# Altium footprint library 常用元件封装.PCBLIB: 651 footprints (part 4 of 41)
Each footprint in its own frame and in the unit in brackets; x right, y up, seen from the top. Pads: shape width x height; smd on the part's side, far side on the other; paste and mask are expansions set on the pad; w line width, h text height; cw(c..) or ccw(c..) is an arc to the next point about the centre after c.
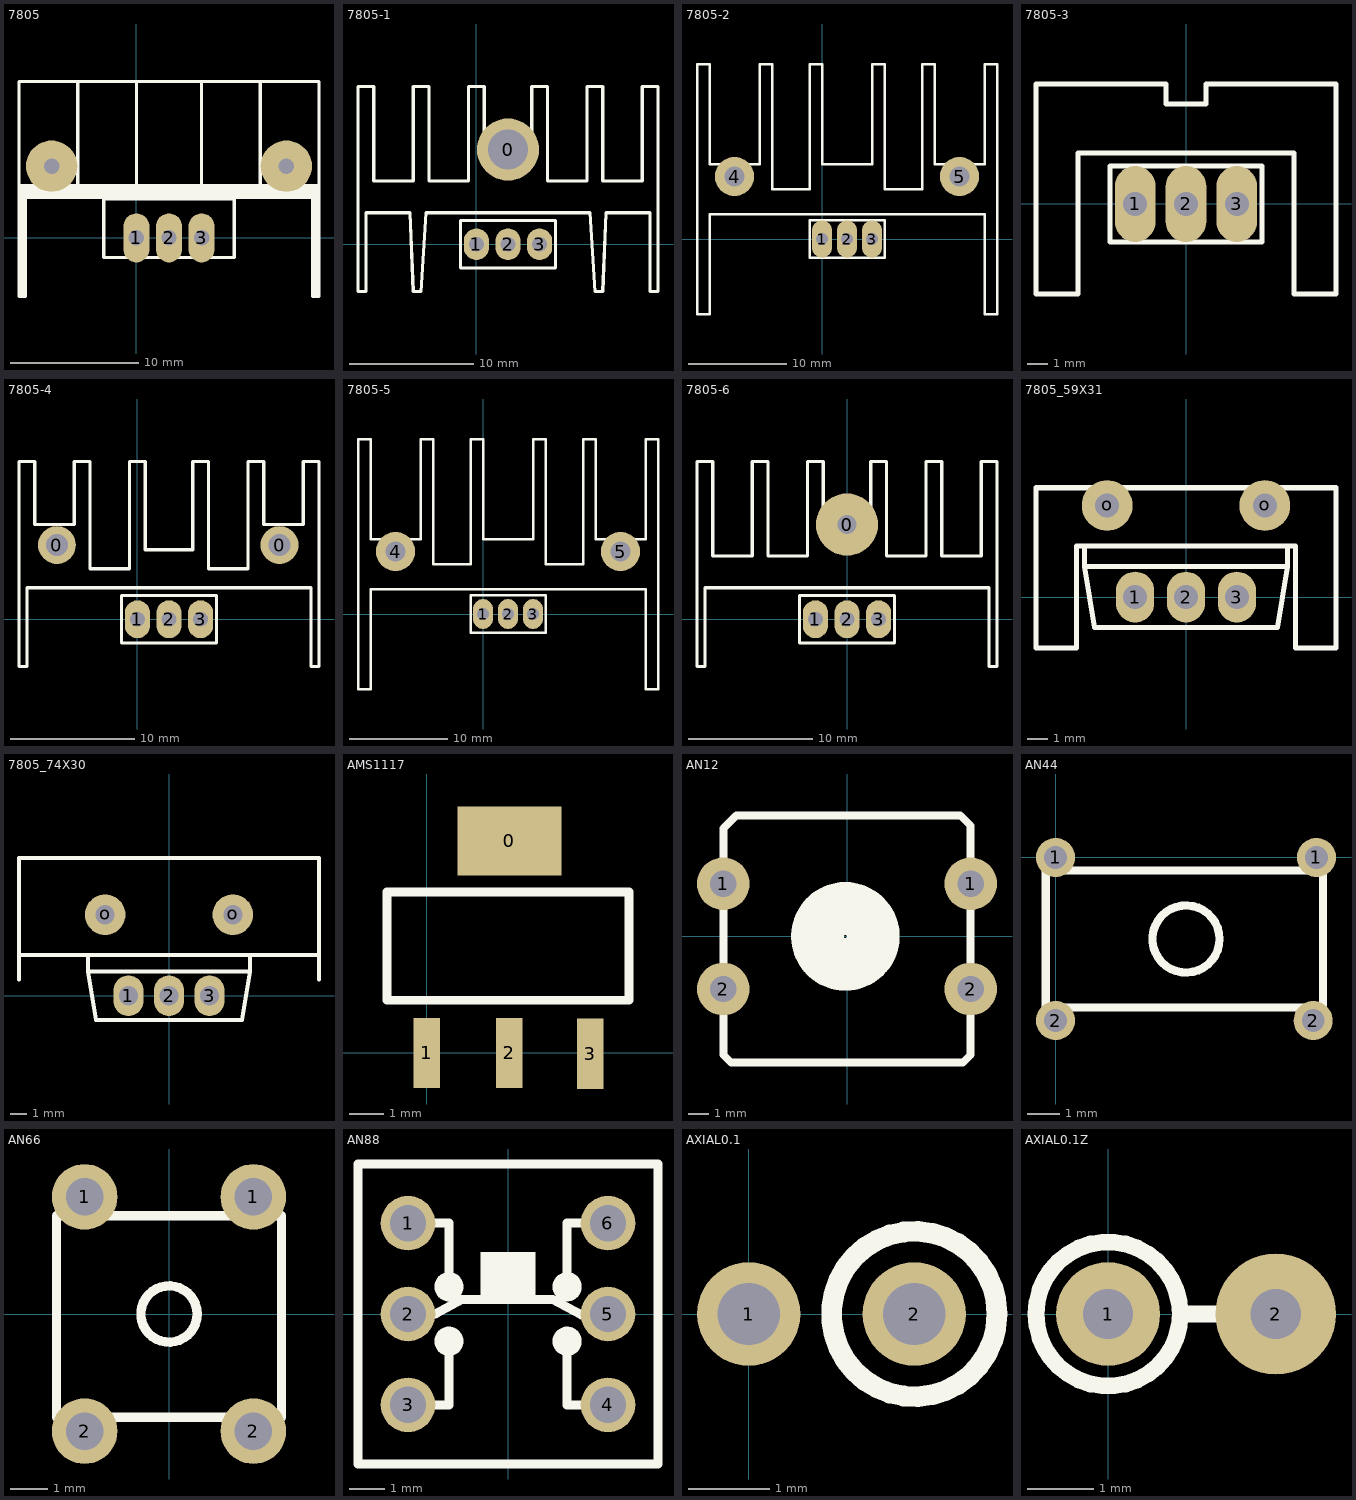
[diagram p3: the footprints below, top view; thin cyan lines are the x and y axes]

## 7805 [mm]
pads (5):
  oval 2.032x3.81 hole 1.2: 1(0,0) 2(2.54,0) 3(5.08,0)
  round 4 hole 1.2: ""(-6.604,5.588) ""(11.684,5.588)
TopOverlay:
  rectangle: -9.144,3.048 14.224,4.064
  rectangle: -9.144,-4.572 -8.636,3.048
  rectangle: 13.716,-4.572 14.224,3.048
  lines w0.254: -9.144,4.064 14.224,4.064 ; -9.144,6.858 -9.144,7.366 ; -8.636,3.048 -8.636,-4.572 -9.144,-4.572 -9.144,12.192 14.224,12.192 14.224,-4.572 13.716,-4.572 13.716,3.048 ; -4.572,4.064 -4.572,12.192 ; 0,4.064 0,12.192 ; 5.08,4.064 5.08,12.192 ; 9.652,4.064 9.652,12.192 ; 12.446,12.192 12.954,12.192 ; -2.54,-1.524 -2.54,3.048 7.62,3.048 7.62,-1.524 -2.54,-1.524

## 7805-1 [mm]
pads (4):
  round 5 hole 3.2: 0(2.54,7.62)
  oval 2.032x2.54 hole 1.2: 1(0,0) 2(2.54,0) 3(5.08,0)
TopOverlay:
  lines w0.254: 0.635,6.35 0.635,12.7 -0.635,12.7 -0.635,5.08 -3.81,5.08 -3.81,12.7 -5.08,12.7 -5.08,5.08 -8.255,5.08 -8.255,12.7 -9.525,12.7 -9.525,-3.81 -8.89,-3.81 -8.89,2.54 -5.334,2.54 -5.08,-3.81 -4.445,-3.81 -4.064,2.54 9.144,2.54 9.525,-3.81 10.16,-3.81 10.414,2.54 13.97,2.54 13.97,-3.81 14.605,-3.81 14.605,12.7 13.335,12.7 13.335,5.08 10.16,5.08 10.16,12.7 8.89,12.7 8.89,5.08 5.715,5.08 5.715,12.7 4.445,12.7 4.445,6.35 ; -1.27,-1.905 -1.27,1.905 6.35,1.905 6.35,-1.905 -1.27,-1.905

## 7805-2 [mm]
pads (5):
  oval 2.032x3.81 hole 1.2: 1(0,0) 2(2.54,0) 3(5.08,0)
  round 4 hole 2: 4(-8.89,6.35) 5(13.97,6.35)
TopOverlay:
  lines w0.254: -12.7,-7.62 -12.7,17.78 -11.43,17.78 -11.43,7.62 -6.35,7.62 -6.35,17.78 -5.08,17.78 -5.08,5.08 -1.27,5.08 -1.27,17.78 0,17.78 0,7.62 5.08,7.62 5.08,17.78 6.35,17.78 6.35,5.08 10.16,5.08 10.16,17.78 11.43,17.78 11.43,7.62 16.51,7.62 16.51,17.78 17.78,17.78 17.78,-7.62 16.51,-7.62 16.51,2.54 -11.43,2.54 -11.43,-7.62 -12.7,-7.62 ; -1.27,-1.905 6.35,-1.905 6.35,1.905 -1.27,1.905 -1.27,-1.905

## 7805-3 [mil]
pads (3):
  oval 80x150 hole 47.24: 1(-100,0) 2(0,0) 3(100,0)
TopOverlay:
  lines w10: -295.28,-177.17 -295.28,236.22 -39.37,236.22 -39.37,196.85 39.37,196.85 39.37,236.22 295.28,236.22 295.28,-177.17 212.6,-177.17 212.6,100 0,100 -212.6,100 -212.6,-177.17 -295.28,-177.17 ; -150,-75 -150,75 150,75 150,-75 -150,-75

## 7805-4 [mil] "17.9mm"
pads (5):
  round 120 hole 70: 0(-255,235) 0(450,235)
  oval 80x120 hole 47.24: 1(0,0) 2(100,0) 3(200,0)
TopOverlay:
  lines w10: -375,-150 -375,500 -325,500 -325,300 -200,300 -200,500 -150,500 -150,160 -25,160 -25,500 25,500 25,220 175,220 175,500 225,500 225,160 350,160 350,500 400,500 400,300 525,300 525,500 575,500 575,-150 550,-150 550,100 -350,100 -350,-150 -375,-150 ; -50,-75 250,-75 250,75 -50,75 -50,-75

## 7805-5 [mm]
pads (5):
  oval 2.032x3.048 hole 1.2: 1(0,0) 2(2.54,0) 3(5.08,0)
  round 4 hole 2: 4(-8.89,6.35) 5(13.97,6.35)
TopOverlay:
  lines w0.254: -12.7,-7.62 -12.7,17.78 -11.43,17.78 -11.43,7.62 -6.35,7.62 -6.35,17.78 -5.08,17.78 -5.08,5.08 -1.27,5.08 -1.27,17.78 0,17.78 0,7.62 5.08,7.62 5.08,17.78 6.35,17.78 6.35,5.08 10.16,5.08 10.16,17.78 11.43,17.78 11.43,7.62 16.51,7.62 16.51,17.78 17.78,17.78 17.78,-7.62 16.51,-7.62 16.51,2.54 -11.43,2.54 -11.43,-7.62 -12.7,-7.62 ; -1.27,-1.905 6.35,-1.905 6.35,1.905 -1.27,1.905 -1.27,-1.905

## 7805-6 [mil]
pads (4):
  round 196.85 hole 59.06: 0(0,300)
  oval 80x120 hole 47.24: 1(-100,0) 2(0,0) 3(100,0)
TopOverlay:
  lines w10: -75,250 -75,500 -125,500 -125,200 -250,200 -250,500 -300,500 -300,200 -425,200 -425,500 -475,500 -475,-150 -450,-150 -450,100 450,100 450,-150 475,-150 475,500 425,500 425,200 300,200 300,500 250,500 250,200 125,200 125,500 75,500 75,250 ; -150,-75 150,-75 150,75 -150,75 -150,-75

## 7805_59X31 [mm]
pads (5):
  oval 1.905x2.54 hole 1.2: 1(-2.54,0) 2(0,0) 3(2.54,0)
  round 2.54 hole 1.2: o(-3.937,4.572) o(3.937,4.572)
TopOverlay:
  lines w0.254: -5.08,2.54 -5.08,1.524 ; 5.08,2.54 5.08,1.524 ; -5.08,1.524 -4.572,-1.524 4.572,-1.524 5.08,1.524 ; -5.08,1.524 5.08,1.524 ; -7.493,-2.54 -7.493,5.461 7.493,5.461 7.493,-2.54 5.461,-2.54 5.461,2.54 -5.461,2.54 -5.461,-2.54 -7.493,-2.54

## 7805_74X30 [mm]
pads (5):
  oval 1.905x2.54 hole 1.2: 1(-2.54,0) 2(0,0) 3(2.54,0)
  round 2.54 hole 1.2: o(-4,5.08) o(4,5.08)
TopOverlay:
  lines w0.254: -9.398,1.016 -9.398,8.636 9.398,8.636 9.398,1.016 ; -9.398,2.54 9.398,2.54 ; -5.08,2.54 -5.08,1.524 ; 5.08,2.54 5.08,1.524 ; -5.08,1.524 -4.572,-1.524 4.572,-1.524 5.08,1.524 ; -5.08,1.524 5.08,1.524

## AMS1117 [mil]
pads (4):
  rect 118.11x78.74 smd: 0(94,241)
  rect 30x80 smd: 1(0,0) 2(94,0) 3(186,-1)
TopOverlay:
  lines w10: -45,60 -45,183 230,183 230,60 -45,60

## AN12 [mil]
pads (4):
  round 100 hole 50: 1(-235,100) 1(235,100) 2(-235,-100) 2(235,-100)
TopOverlay:
  circle w100: c-3.15,0 r53.15
  lines w15: -235,-225 -220,-240 220,-240 235,-225 235,210 215,230 -210,230 -235,205 -235,-225

## AN44 [mm]
pads (4):
  round 1.2 hole 0.7: 1(0,0) 1(8,0) 2(0,-5) 2(7.9,-5)
TopOverlay:
  circle w0.254: c4,-2.5 r1.03
  lines w0.254: -0.3,-4.6 -0.3,-0.4 8.2,-0.4 8.2,-4.6 -0.3,-4.6

## AN66 [mil]
pads (4):
  round 70 hole 40: 1(-90,125) 1(90,125) 2(-90,-125) 2(90,-125)
TopOverlay:
  circle w10: c0,0 r30
  lines w10: -120,-110 120,-110 120,105 -120,105 -120,-110

## AN88 [mil]
pads (6):
  round 60 hole 40: 1(-110,100) 2(-110,0) 3(-110,-100) 4(110,-100) 5(110,0) 6(110,100)
TopOverlay:
  circle w18: c-65,30 r7.07
  circle w18: c65,30 r7.07
  circle w18: c65,-30 r7.07
  circle w18: c-65,-30 r7.07
  rectangle: -30,16 30,68
  lines w10: -110,-100 -65,-100 -65,-40 ; -110,0 -80,0 -51,16 49,16 81,-1 109,-1 110,0 ; -110,100 -65,100 -65,30 ; 65,-40 65,-100 110,-100 ; 65,40 65,100 110,100 ; -165,-165 -165,165 165,165 165,-165 -165,-165

## AXIAL0.1 [mil]
pads (2):
  round 50 hole 30: 1(0,0) 2(80,0)
TopOverlay:
  circle w10: c80,0 r40

## AXIAL0.1Z [mil]
pads (2):
  round 62 hole 30: 1(0,0)
  round 72 hole 30: 2(100,0)
TopOverlay:
  circle w10: c0,0 r43.01
  lines w10: 45,0 70,0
